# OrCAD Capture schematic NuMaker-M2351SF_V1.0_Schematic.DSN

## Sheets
1 Nu-Link2-Me: size A3; title: Nu-Link2-Me; rev: 1.0; company: CMHuang; note: Nu-Link2-Me
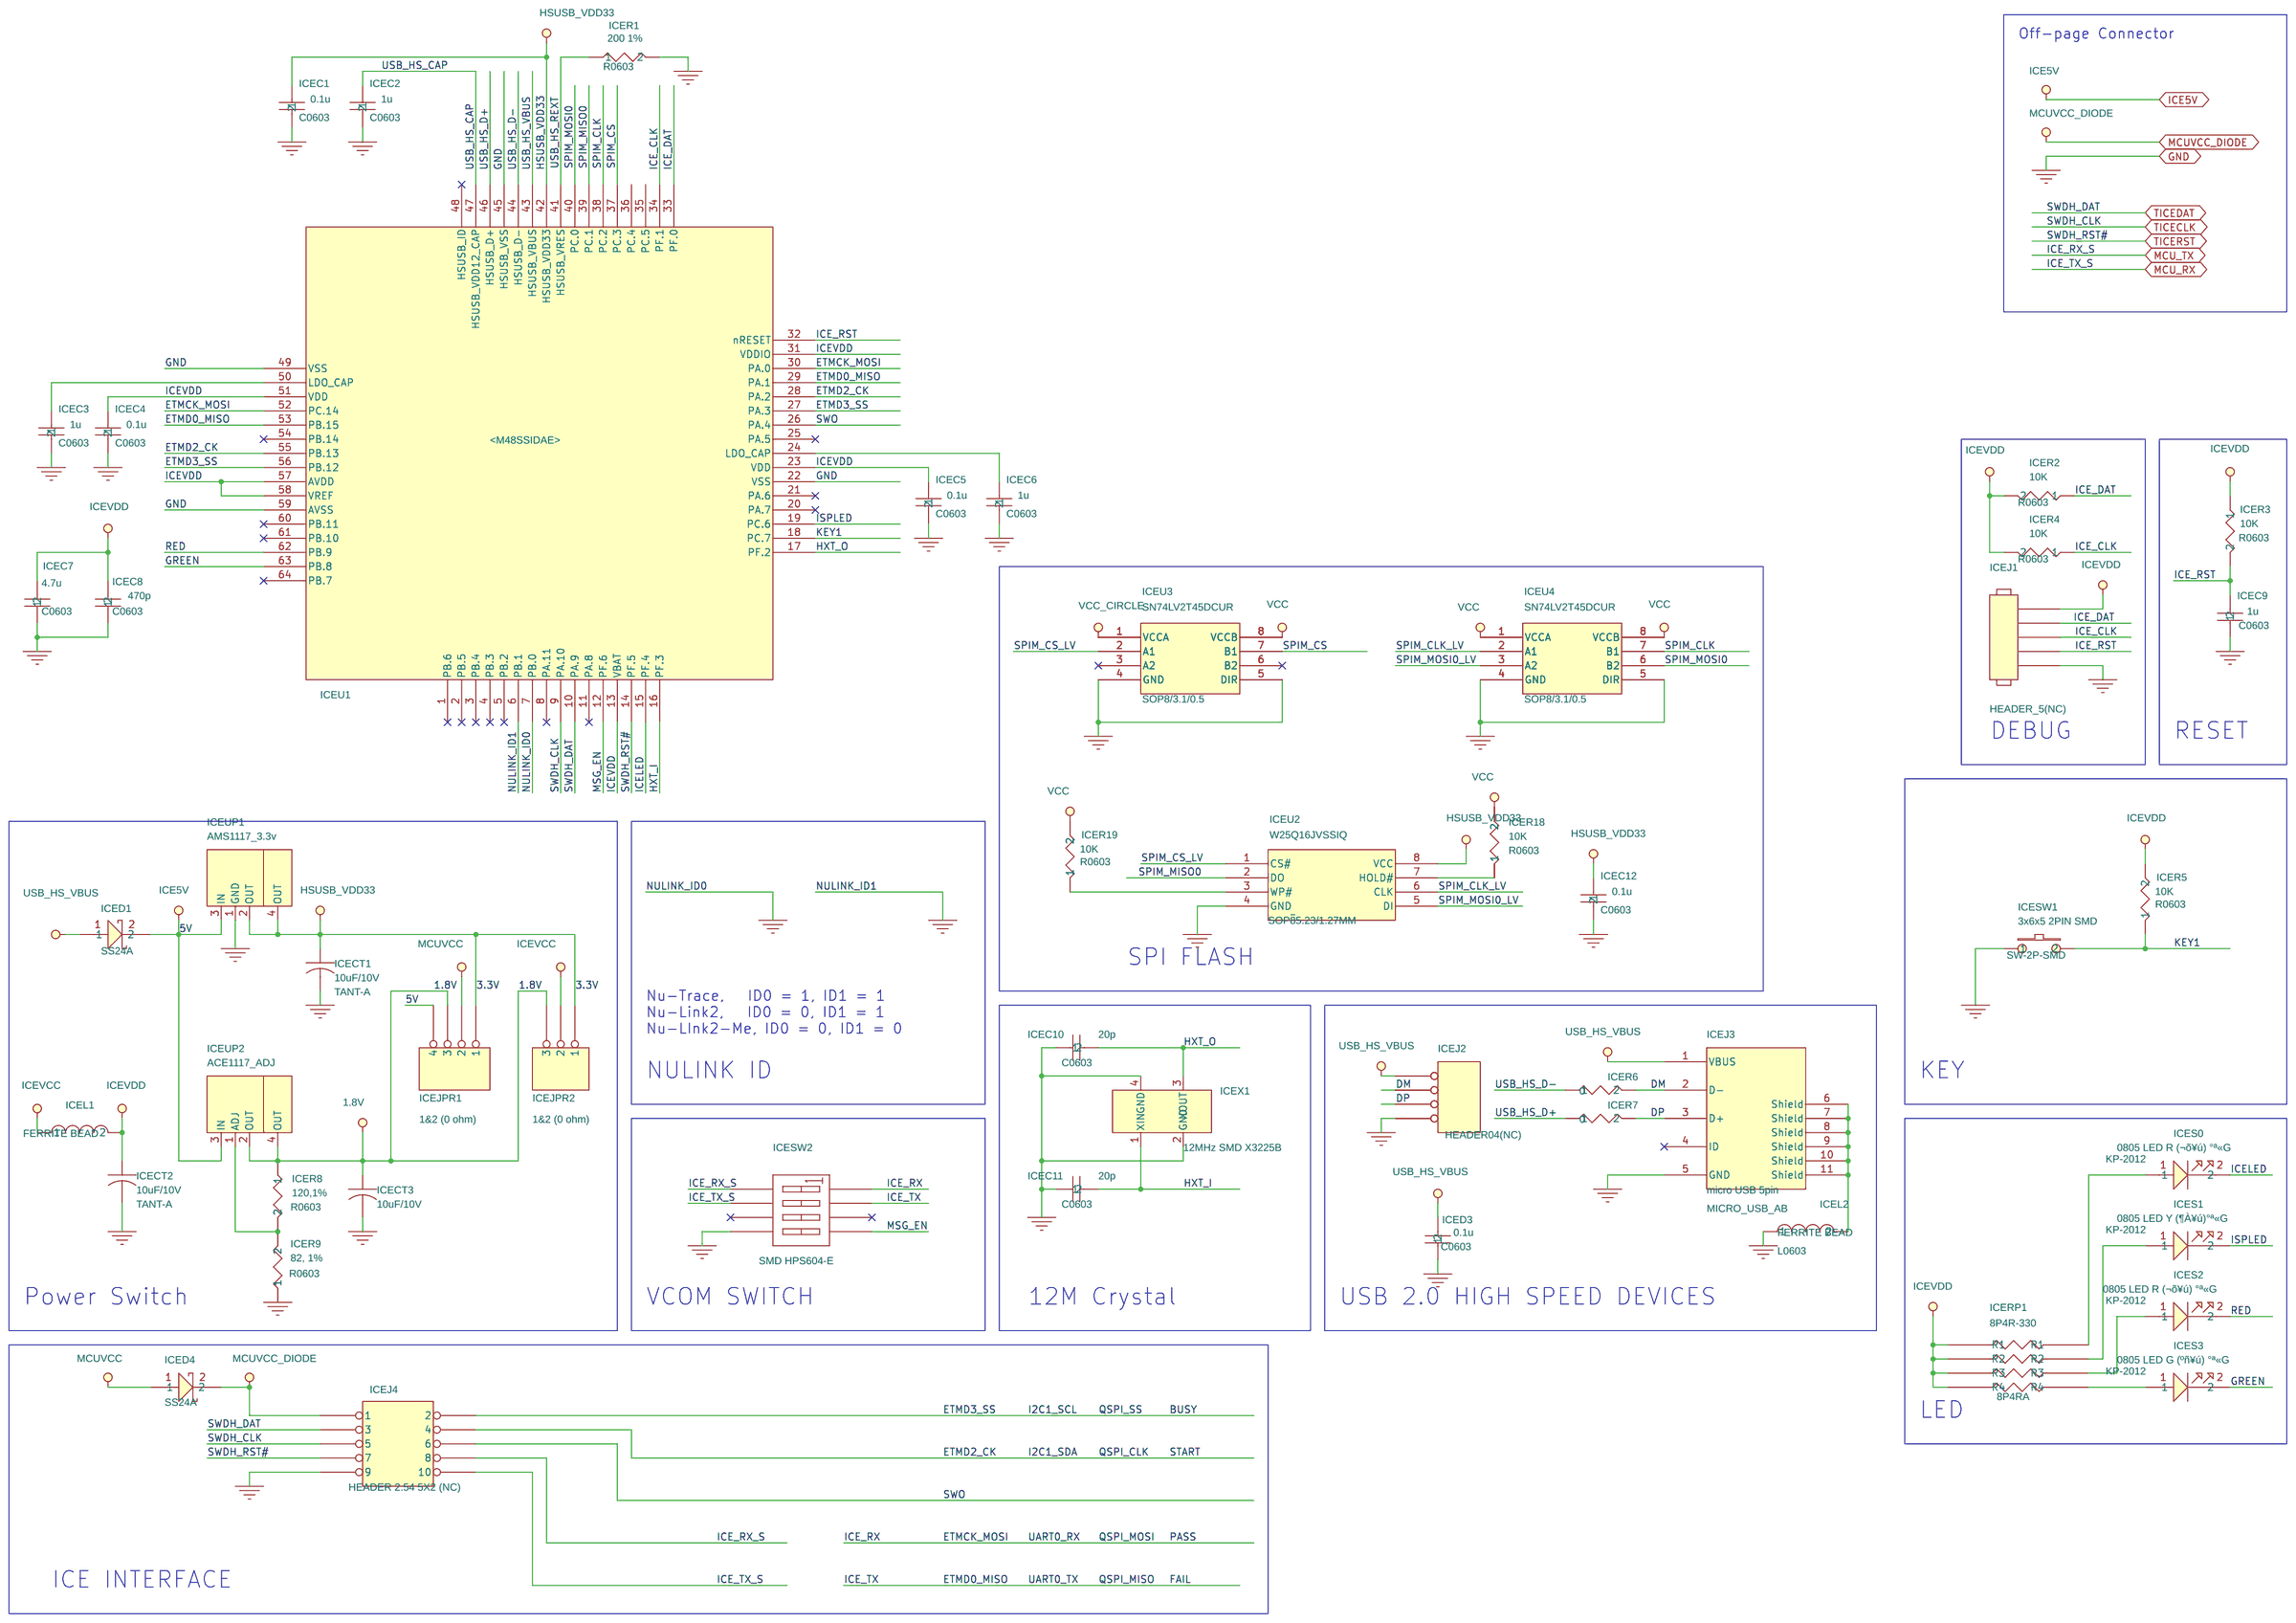
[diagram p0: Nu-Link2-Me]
2 M2351SFSIAAP: size Custom; title: M2351SFSIAAP; rev: v1.0; note: NuMaker-M2351SF
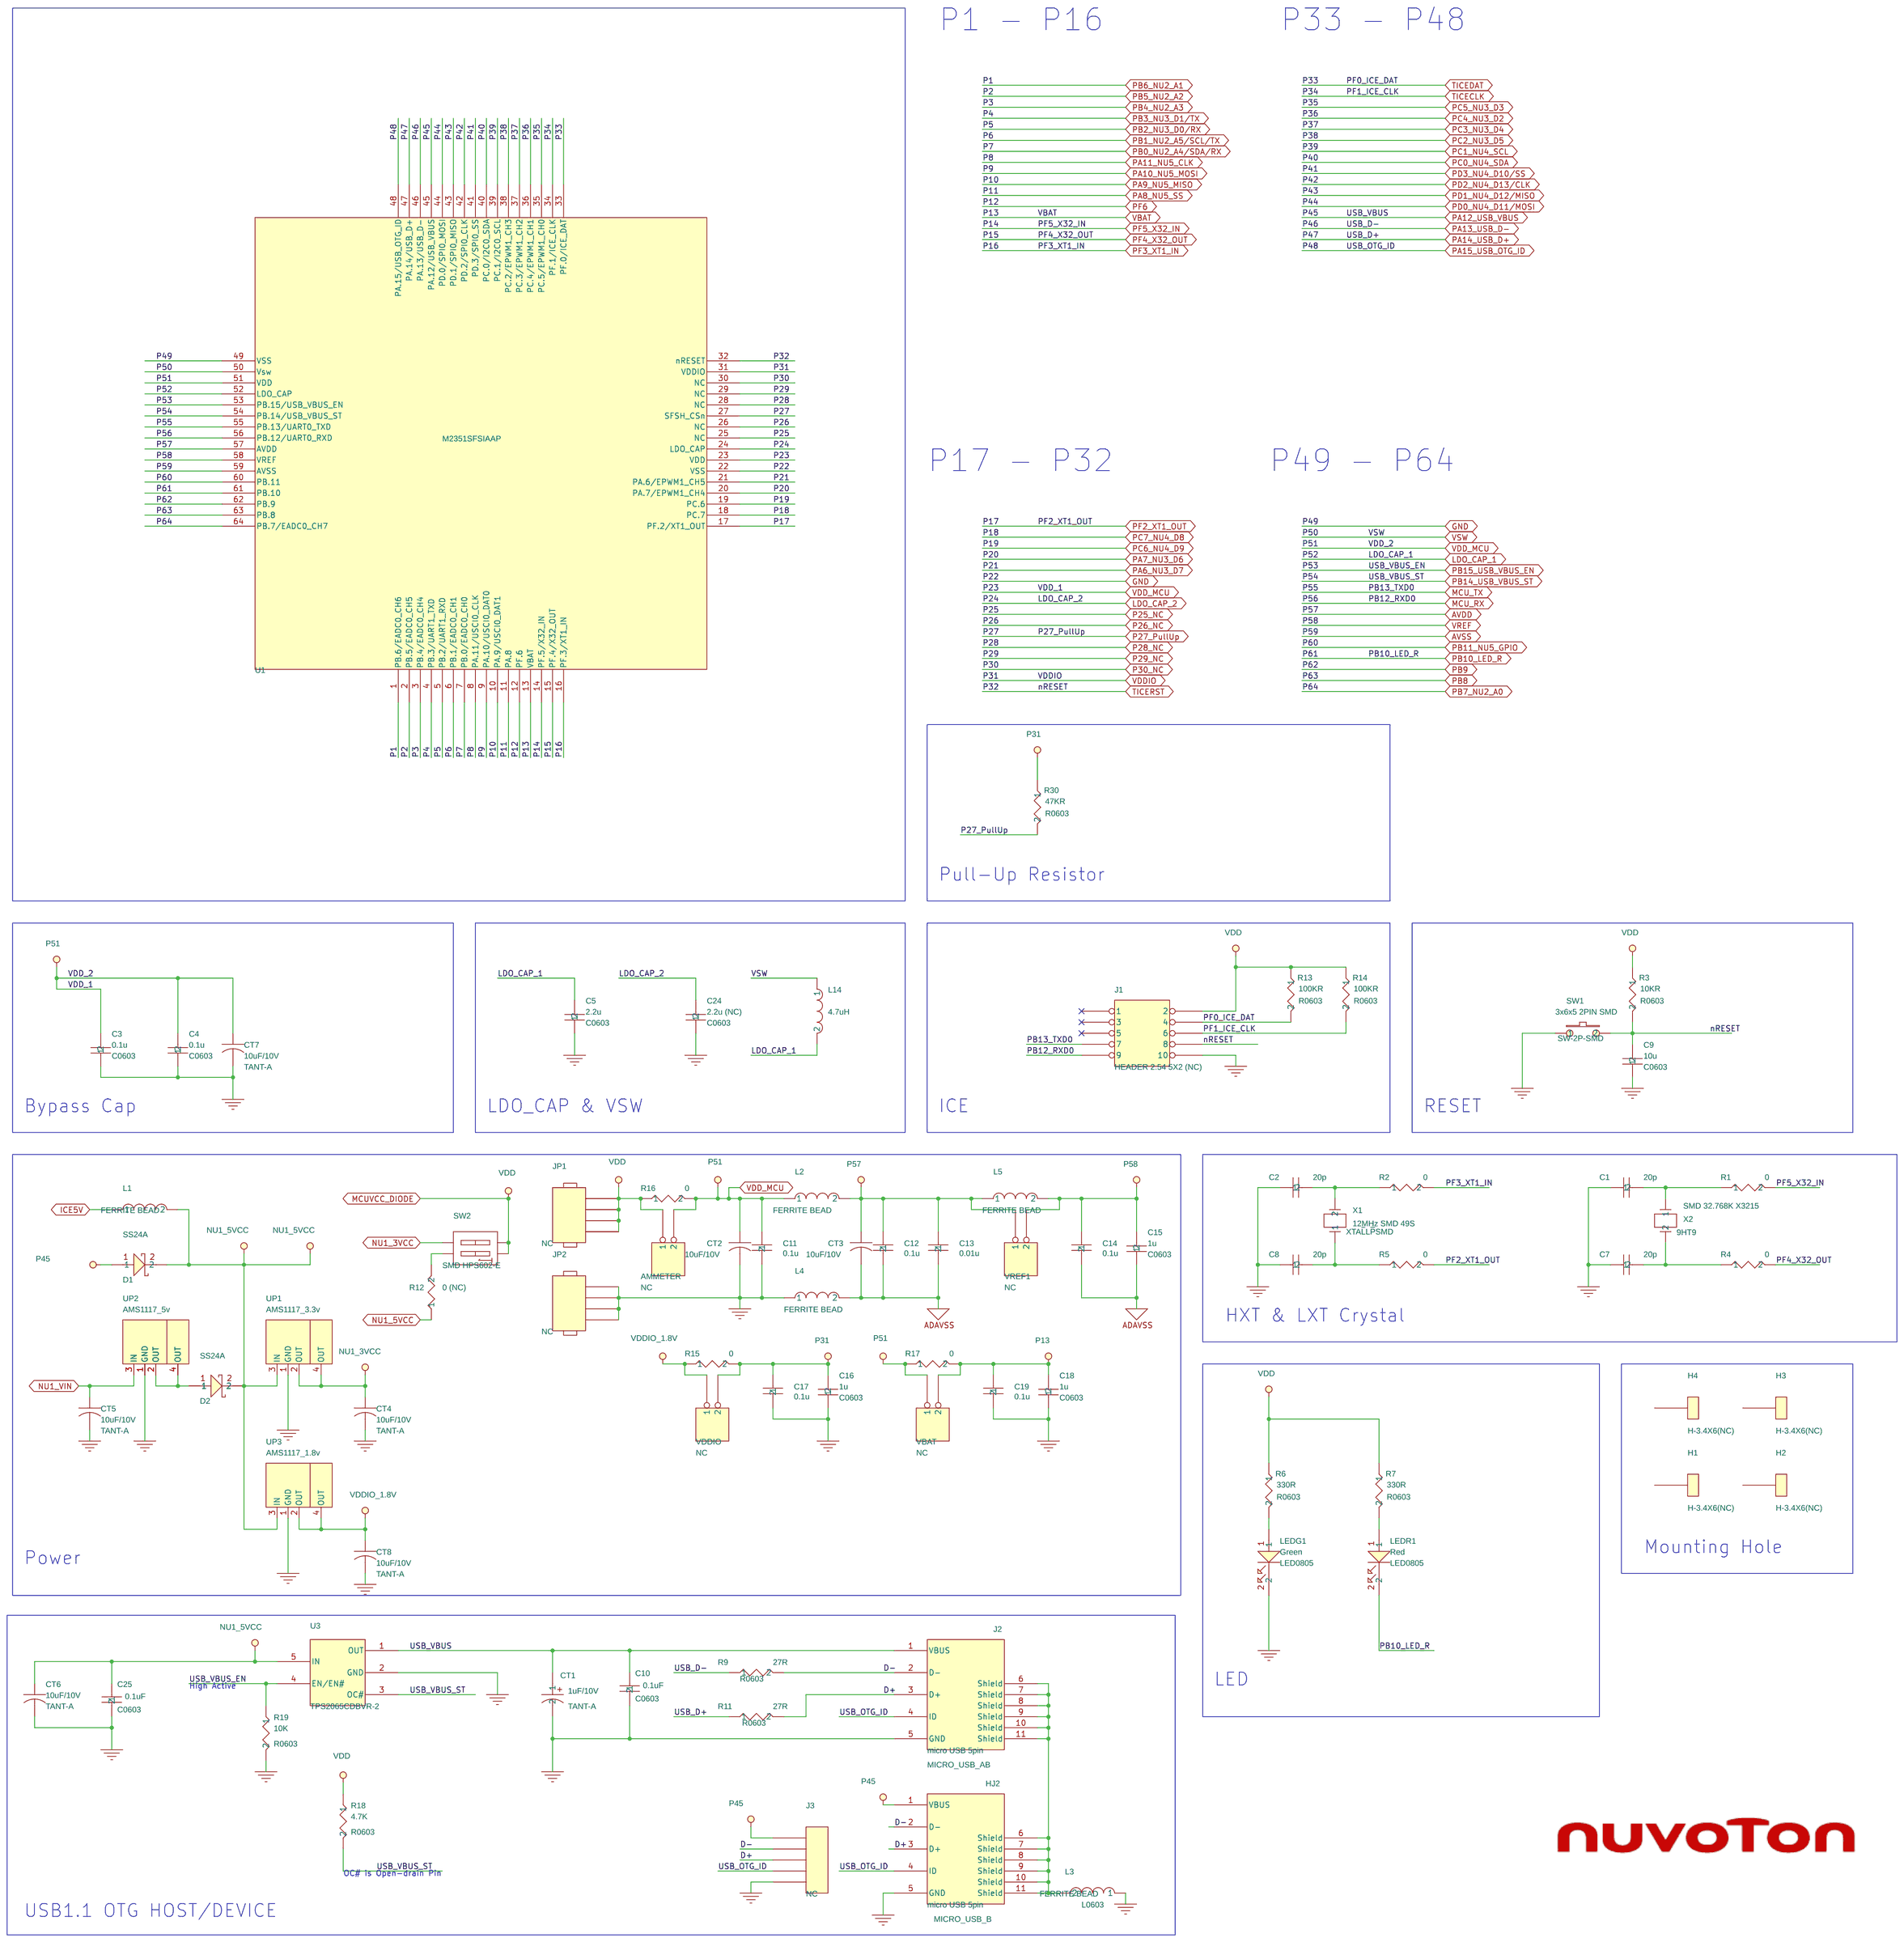
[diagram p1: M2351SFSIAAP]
3 Ext. Connector: size Custom; title: Ext. Connector; rev: v1.0; note: NuMaker-M2351SF
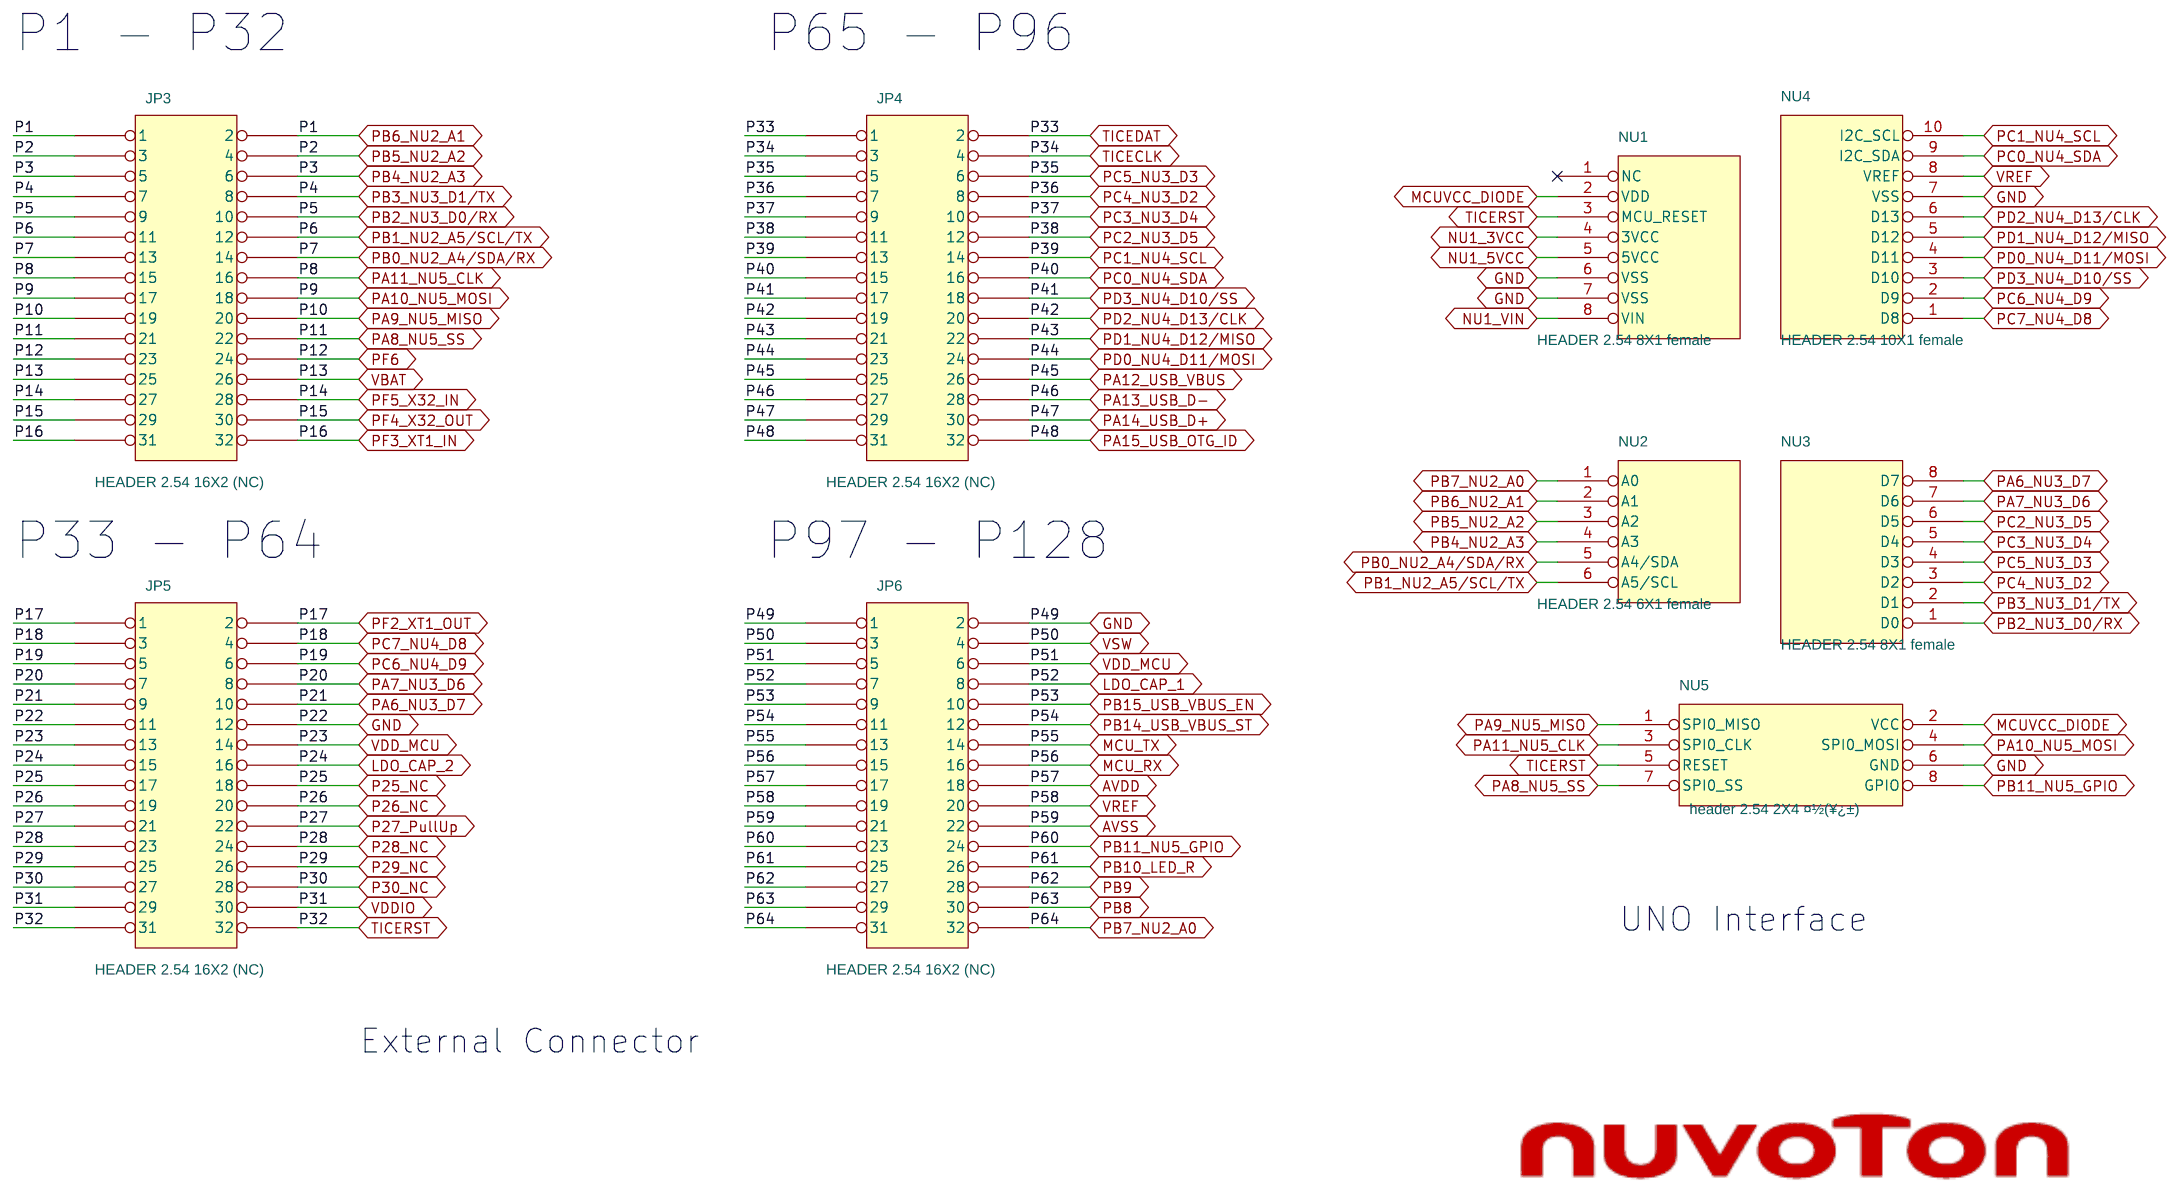
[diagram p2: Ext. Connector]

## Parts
sheet Ext. Connector
JP3  HEADER 2.54 16X2 (NC)  [HEADER16X2]
JP4  HEADER 2.54 16X2 (NC)  [HEADER16X2]
JP5  HEADER 2.54 16X2 (NC)  [HEADER16X2]
JP6  HEADER 2.54 16X2 (NC)  [HEADER16X2]
NU1  HEADER 2.54 8X1 female  [SIP-8P]
NU2  HEADER 2.54 6X1 female  [SIP-6P]
NU3  HEADER 2.54 8X1 female  [SIP-8P]
NU4  HEADER 2.54 10X1 female  [SIP-10P]
NU5  header 2.54 2X4 ¤½(¥¿­±)  [HEADER4X2]
sheet M2351SFSIAAP
AMMETER  NC  [HEADER2X1]
C1  20p  [C0603]
C2  20p  [C0603]
C3  0.1u  [C0603]
C4  0.1u  [C0603]
C5  2.2u  [C0603]
C7  20p  [C0603]
C8  20p  [C0603]
C9  10u  [C0603]
C10  0.1uF  [C0603]
C11  0.1u  [C0603]
C12  0.1u  [C0603]
C13  0.01u  [C0603]
C14  0.1u  [C0603]
C15  1u  [C0603]
C16  1u  [C0603]
C17  0.1u  [C0603]
C18  1u  [C0603]
C19  0.1u  [C0603]
C24  2.2u (NC)  [C0603]
C25  0.1uF  [C0603]
CT1  1uF/10V  [TANT-A]
CT2  10uF/10V  [TANT-A]
CT3  10uF/10V  [TANT-A]
CT4  10uF/10V  [TANT-A]
CT5  10uF/10V  [TANT-A]
CT6  10uF/10V  [TANT-A]
CT7  10uF/10V  [TANT-A]
CT8  10uF/10V  [TANT-A]
D1  SS24A  [RB060L]
D2  SS24A  [RB060L]
H1  H-3.4X6(NC)  [H-3.4X6]
H2  H-3.4X6(NC)  [H-3.4X6]
H3  H-3.4X6(NC)  [H-3.4X6]
H4  H-3.4X6(NC)  [H-3.4X6]
HJ2  micro USB 5pin  [MICRO_USB_B]
J1  HEADER 2.54 5X2 (NC)  [HEADER5X2]
J2  micro USB 5pin  [MICRO_USB_AB]
J3  NC  [HEADER5X1]
JP1  NC  [header1x4]
JP2  NC  [header1x4]
L1  FERRITE BEAD  [L0603]
L2  FERRITE BEAD  [L0603]
L3  FERRITE BEAD  [L0603]
L4  FERRITE BEAD  [L0603]
L5  FERRITE BEAD  [L0603]
L14  4.7uH  [L-VLF403215MT]
LEDG1  Green  [LED0805]
LEDR1  Red  [LED0805]
R1  0  [R0603]
R2  0  [R0603]
R3  10KR  [R0603]
R4  0  [R0603]
R5  0  [R0603]
R6  330R  [R0603]
R7  330R  [R0603]
R9  27R  [R0603]
R11  27R  [R0603]
R12  0 (NC)  [R0603]
R13  100KR  [R0603]
R14  100KR  [R0603]
R15  0  [R0603]
R16  0  [R0603]
R17  0  [R0603]
R18  4.7K  [R0603]
R19  10K  [R0603]
R30  47KR  [R0603]
SW1  3x6x5 2PIN SMD  [SW-2P-SMD]
SW2  SMD HPS602-E  [SW1X2]
U1  M2353SIAAE  [MCU_LQFP_64_7X7]
U3  TPS2065CDBVR-2  [SOT23-5]
UP1  AMS1117_3.3v  [SOT-223-1]
UP2  AMS1117_5v  [SOT-223-1]
UP3  AMS1117_1.8v  [SOT-223-1]
VBAT  NC  [HEADER2X1]
VDDIO  NC  [HEADER2X1]
VREF1  NC  [HEADER2X1]
X1  12MHz SMD 49S  [XTAL\LP\SMD]
X2  SMD 32.768K X3215  [9HT9]
sheet Nu-Link2-Me
ICEC1  0.1u  [C0603]
ICEC2  1u  [C0603]
ICEC3  1u  [C0603]
ICEC4  0.1u  [C0603]
ICEC5  0.1u  [C0603]
ICEC6  1u  [C0603]
ICEC7  4.7u  [C0603]
ICEC8  470p  [C0603]
ICEC9  1u  [C0603]
ICEC10  20p  [C0603]
ICEC11  20p  [C0603]
ICEC12  0.1u  [C0603]
ICECT1  10uF/10V  [TANT-A]
ICECT2  10uF/10V  [TANT-A]
ICECT3  10uF/10V  [TANT-A]
ICED1  SS24A  [RB060L]
ICED3  0.1u  [C0603]
ICED4  SS24A  [RB060L]
ICEJ1  HEADER_5(NC)  [HEADER5X1]
ICEJ2  HEADER04(NC)  [HEADER04]
ICEJ3  micro USB 5pin  [MICRO_USB_AB]
ICEJ4  HEADER 2.54 5X2 (NC)  [HEADER5X2]
ICEJPR1  1&2 (0 ohm)  [R0603X3]
ICEJPR2  1&2 (0 ohm)  [R0603X2]
ICEL1  FERRITE BEAD  [L0603]
ICEL2  FERRITE BEAD  [L0603]
ICER1  200 1%  [R0603]
ICER2  10K  [R0603]
ICER3  10K  [R0603]
ICER4  10K  [R0603]
ICER5  10K  [R0603]
ICER6  0  [R0603]
ICER7  0  [R0603]
ICER8  120,1%  [R0603]
ICER9  82, 1%  [R0603]
ICER18  10K  [R0603]
ICER19  10K  [R0603]
ICERP1  8P4R-330  [8P4RA]
ICES0  0805 LED R (¬õ¥ú) °ª«G  [KP-2012]
ICES1  0805 LED Y (¶À¥ú)°ª«G  [KP-2012]
ICES2  0805 LED R (¬õ¥ú) °ª«G  [KP-2012]
ICES3  0805 LED G (ºñ¥ú) °ª«G  [KP-2012]
ICESW1  3x6x5 2PIN SMD  [SW-2P-SMD]
ICESW2  SMD HPS604-E  [SW1X4]
ICEU1  M48SSIDAE  [LQFP64_7x7_M48SSIDAE]
ICEU2  W25Q16JVSSIQ  [SOP8\5.23/1.27MM]
ICEU3  SN74LV2T45DCUR  [SOP8/3.1/0.5]
ICEU4  SN74LV2T45DCUR  [SOP8/3.1/0.5]
ICEUP1  AMS1117_3.3v  [SOT-223-1]
ICEUP2  ACE1117_ADJ  [SOT-223-1]
ICEX1  12MHz SMD X3225B  [CRYSTAL_SMD]

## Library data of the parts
JP3 = HEADER_16X2_2
JP4 = HEADER_16X2_3
JP5 = HEADER_16X2_1
JP6 = HEADER_16X2
NU1 = POWER_CONNECT_0
NU2 = ADC_CONNECT_0
NU3 = PWM0_CONNECT_0
NU4 = PWM1_CONNECT_1
NU5 = NuEdu_NU7
AMMETER = HEADER_2_2
C1 = C_20p_3
C2 = C_20p
C3 = CAP-C: Package: 0603; element_no: C0004
C4 = CAP-C_1: Package: 0603; element_no: C0004
C5 = CAP-C_3: Package: 0603; element_no: C0006
C7 = C_20p_1
C8 = C_20p_2
C9 = CAP-C_6: Package: 0603; element_no: C0006
C10 = CAP-B_1: Package: 0603
C11 = C_0.1u_1: element_no: C0004
C12 = C_0.1u_3: element_no: C0004
C13 = C_0.1u_5: element_no: C0003
C14 = C_0.1u_2: element_no: C0004
C15 = CAP-C_4: Package: 0603; element_no: C0006
C16 = CAP-C_7: Package: 0603; element_no: C0006
C17 = C_0.1u_4: element_no: C0004
C18 ICEC6 = CAP-C_2: Package: 0603; element_no: C0006
C19 = C_0.1u: element_no: C0004
C24 = CAP-C_5: Package: 0603; element_no: C0006
C25 = CAP-B: Package: 0603
CT1 = CAP-T: Package: TANT-R
CT2-CT8 ICECT1-ICECT3 = C_10uF_10V
D1 ICED4 = D_SS24A
D2 ICED1 = D_SS24A_1
H1-H4 = TEST_POINT
HJ2 ICEJ3 J2 = micro_USB_5pin_0
ICEJ4 J1 = HEADER_5X2
J3 = CON5
JP1 JP2 = HEADER_4_v2
L1 = FERRITE_BEAD_4
L2 = FERRITE_BEAD_3
L3 = FERRITE_BEAD_2
ICEL2 L4 = FERRITE_BEAD_1
ICEL1 L5 = FERRITE_BEAD
L14 = INDUCTOR
LEDG1 = LED_0_1: Package: KP-2012; Vendor: Kingbright
LEDR1 = LED_0: Package: KP-2012; Vendor: Kingbright
R1 = R_0_1
R2 = R_0_5
ICER1 R3 = R_0_6: Package: 0603
R4 = R_0_16
R5 = R_0_4
R6 = R_0_12: Package: 0603
ICER2 R7 = R_0: Package: 0603
ICER8 R9 = R_0_8: Package: 0603
R11 = R_0_15: Package: 0603
R12 = R_0_11
R13 = R_0_10: Package: 0603
R14 = R_0_13: Package: 0603
R15 = R_0_9
R16 = R_0_2
R17 = R_0_17
ICER9 R18 = R_0_7: Package: 0603
ICER18 R19 = R_0_3: Package: 0603
R30 = R_0_14: Package: 0603
ICESW1 SW1 = SW_PUSHBUTTON_0
SW2 = SW_DIP-4_2
U1 = M2353SIAAE_2: M2351SIAAE: M2351SFSIAAP
U3 = NCT3520U
ICEUP1 UP1-UP3 = TO-247_Regulator_10
VBAT = HEADER_2_1
VDDIO = HEADER_2_3
VREF1 = HEADER_2
X1 = Xtal_12MHz
X2 = Xtal_32.768K
ICEC1 = CAP-C_8: Package: 0603; element_no: C0004
ICEC2 = CAP-C_11: Package: 0603; element_no: C0006
ICEC3 = CAP-C_10: Package: 0603; element_no: C0006
ICEC4 = CAP-C_12: Package: 0603; element_no: C0004
ICEC5 = CAP-C_5: Package: 0603; element_no: C0004
ICEC7 = CAP-C_3: Package: 0603
ICEC8 = CAP-C_6: Package: 0603
ICEC9 = CAP-C_9: Package: 0603; element_no: C0006
ICEC10 = CAP-C_1: Package: 0603
ICEC11 = CAP-C: Package: 0603
ICEC12 = CAP-C_4: Package: 0603; element_no: C0004
ICED3 = CAP-C_7: Package: 0603; element_no: C0004
ICEJ1 = HEADER_5
ICEJ2 = HEADER_4
ICEJPR1 = HEADER_3_0
ICEJPR2 = HEADER_3
ICER3 = R_0_4: Package: 0603
ICER4 = R_0_1: Package: 0603
ICER5 = R_0_5: Package: 0603
ICER6 = R_33_1
ICER7 = R_33
ICER19 = R_0_2: Package: 0603
ICERP1 = R-PACK8_0
ICES0 = LED_0_1: Vendor: Kingbright
ICES1 = LED_0_3: Vendor: Kingbright
ICES2 = LED_0_2: Vendor: Kingbright
ICES3 = LED_0: Vendor: Kingbright
ICESW2 = SW_DIP-4_SM
ICEU1 = M487SIDAE_0: M487SIDAE: <M48SSIDAE>
ICEU2 = W25P10_20_40_SOIC_0: Package: SOP8; Vendor: WINBOND
ICEU3 ICEU4 = SN74LV2T45
ICEUP2 = TO-247_Regulator_0
ICEX1 = Crystal_SMD_1

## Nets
1.8V: ICECT3.1 ICEJPR1.3 ICEJPR2.3 ICER8.1 ICEUP2.2(OUT) ICEUP2.4(OUT)
3.3V: ICEC1.1 ICEC12.1 ICECT1.1 ICEJPR1.1 ICEJPR2.1 ICER18.2 ICER19.2 ICEU1.42(HSUSB_VDD33) ICEU2.8(VCC) ICEU3.1(VCCA) ICEU4.1(VCCA) ICEUP1.2(OUT) ICEUP1.4(OUT)
AVDD: C12.1 C13.1 CT3.1 JP6.17 JP6.18 L2.2 L5.1 U1.57(AVDD) VREF1.1
AVSS: C12.2 C13.2 C14.2 C15.1 CT3.2 JP6.21 JP6.22 L4.2 U1.59(AVSS)
GND: C1.1 C2.1 C3.1 C4.1 C5.1 C7.1 C8.1 C9.1 C10.2 C11.2 C16.1 C17.2 C18.1 C19.2 C24.1 C25.2 CT1.2 CT2.2 CT4.2 CT5.2 CT6.2 CT7.2 CT8.2 HJ2.5(GND) ICEC1.2 ICEC2.2 ICEC3.2 ICEC4.2 ICEC5.2 ICEC6.2 ICEC7.1 ICEC8.1 ICEC9.1 ICEC10.1 ICEC11.1 ICEC12.2 ICECT1.2 ICECT2.2 ICECT3.2 ICED3.1 ICEJ1.5 ICEJ2.4 ICEJ3.5(GND) ICEJ4.9 ICEL2.1 ICER1.2 ICER9.1 ICESW1.1 ICESW2.4(A4) ICEU1.6(PB.1) ICEU1.7(PB.0) ICEU1.22(VSS) ICEU1.45(HSUSB_VSS) ICEU1.49(VSS) ICEU1.59(AVSS) ICEU2.4(GND) ICEU3.4(GND) ICEU3.5(DIR) ICEU4.4(GND) ICEU4.5(DIR) ICEUP1.1(GND) ICEX1.2(GND) ICEX1.4(GND) J1.10 J2.5(GND) J3.5 JP2.1 JP2.2 JP2.3 JP2.4 JP5.11 JP5.12 JP6.1 JP6.2 L3.1 L4.1 LEDG1.2 NU1.6(VSS) NU1.7(VSS) NU4.7(VSS) NU5.6(GND) R19.2 SW1.1 U1.22(VSS) U1.49(VSS) U3.2(GND) UP1.1(GND) UP2.1(GND) UP3.1(GND)
VBAT: C18.2 C19.1 JP3.25 JP3.26 R17.2 U1.13(VBAT) VBAT.2
VDD: AMMETER.1 ICED4.2 ICEJ4.1 J1.2 JP1.1 JP1.2 JP1.3 JP1.4 NU1.2(VDD) NU5.2(VCC) R3.1 R6.1 R7.1 R13.1 R14.1 R16.1 R18.1 SW2.3(B1) SW2.4(B2)
VDD_MCU: AMMETER.2 C3.2 C4.2 C11.1 CT2.1 CT7.1 JP5.13 JP5.14 JP6.5 JP6.6 L2.1 R16.2 R17.1 U1.23(VDD) U1.51(VDD) VBAT.1
VDDIO: C16.2 C17.1 JP5.29 JP5.30 R15.2 R30.1 U1.31(VDDIO) VDDIO.2
VDDIO_1.8V: CT8.1 R15.1 UP3.2(OUT) UP3.4(OUT) VDDIO.1
BUSY: ICEJ4.2 ICEU1.27(PA.3) ICEU1.56(PB.12)
D+: HJ2.3(D+) J2.3(D+) J3.3 R11.2
D-: HJ2.2(D-) J2.2(D-) J3.2 R9.2
DM: ICEJ2.2 ICEJ3.2(D-) ICER6.2
DP: ICEJ2.3 ICEJ3.3(D+) ICER7.2
ETMD2_CK: ICEJ4.4 ICEU1.28(PA.2) ICEU1.55(PB.13)
GREEN: ICES3.2 ICEU1.63(PB.8)
HXT_I: ICEC11.2 ICEU1.16(PF.3) ICEX1.1(XIN)
HXT_O: ICEC10.2 ICEU1.17(PF.2) ICEX1.3(XOUT)
ICE5V: ICED1.2 ICEJPR1.4 ICEUP1.3(IN) ICEUP2.3(IN) L1.1
ICE_CLK: ICEJ1.3 ICER4.1 ICEU1.34(PF.1)
ICE_DAT: ICEJ1.2 ICER2.1 ICEU1.33(PF.0)
ICE_RST: ICEC9.2 ICEJ1.4 ICER3.2 ICEU1.32(nRESET)
ICE_RX: ICESW2.8(B1) ICEU1.30(PA.0) ICEU1.52(PC.14)
ICE_TX: ICESW2.7(B2) ICEU1.29(PA.1) ICEU1.53(PB.15)
ICELED: ICES0.2 ICEU1.15(PF.4)
ICEVCC: ICEJPR2.2 ICEL1.1
ICEVDD: ICEC4.1 ICEC5.1 ICEC7.2 ICEC8.2 ICECT2.1 ICEJ1.1 ICEL1.2 ICER2.2 ICER3.1 ICER4.2 ICER5.2 ICERP1.1(R1) ICERP1.3(R2) ICERP1.5(R3) ICERP1.7(R4) ICEU1.13(VBAT) ICEU1.23(VDD) ICEU1.31(VDDIO) ICEU1.51(VDD) ICEU1.57(AVDD) ICEU1.58(VREF) ICEU3.8(VCCB) ICEU4.8(VCCB)
ISPLED: ICES1.2 ICEU1.19(PC.6)
KEY1: ICER5.1 ICESW1.2 ICEU1.18(PC.7)
LDO_CAP_1: C5.2 JP6.7 JP6.8 L14.2 U1.52(LDO_CAP)
LDO_CAP_2: C24.2 JP5.15 JP5.16 U1.24(LDO_CAP)
MCU_RX: ICEJ4.10 ICESW2.2(A2) J1.9 JP6.15 JP6.16 U1.56(PB.12/UART0_RXD)
MCU_TX: ICEJ4.8 ICESW2.1(A1) J1.7 JP6.13 JP6.14 U1.55(PB.13/UART0_TXD)
MCUVCC: ICED4.1 ICEJPR1.2
MSG_EN: ICESW2.5(B4) ICEU1.12(PF.6)
NU1_3VCC: CT4.1 NU1.4(3VCC) SW2.2(A2) UP1.2(OUT) UP1.4(OUT)
NU1_5VCC: C25.1 CT6.1 D1.2 D2.2 L1.2 NU1.5(5VCC) R12.1 U3.5(IN) UP1.3(IN) UP3.3(IN)
NU1_VIN: CT5.1 NU1.8(VIN) UP2.3(IN)
P25_NC: JP5.17 JP5.18 U1.25(NC)
P26_NC: JP5.19 JP5.20 U1.26(NC)
P27_PullUp: JP5.21 JP5.22 R30.2 U1.27(SFSH_CSn)
P28_NC: JP5.23 JP5.24 U1.28(NC)
P29_NC: JP5.25 JP5.26 U1.29(NC)
P30_NC: JP5.27 JP5.28 U1.30(NC)
PA6_NU3_D7: JP5.9 JP5.10 NU3.8(D7) U1.21(PA.6/EPWM1_CH5)
PA7_NU3_D6: JP5.7 JP5.8 NU3.7(D6) U1.20(PA.7/EPWM1_CH4)
PA8_NU5_SS: JP3.21 JP3.22 NU5.7(SPI0_SS) U1.11(PA.8)
PA9_NU5_MISO: JP3.19 JP3.20 NU5.1(SPI0_MISO) U1.10(PA.9/USCI0_DAT1)
PA10_NU5_MOSI: JP3.17 JP3.18 NU5.4(SPI0_MOSI) U1.9(PA.10/USCI0_DAT0)
PA11_NU5_CLK: JP3.15 JP3.16 NU5.3(SPI0_CLK) U1.8(PA.11/USCI0_CLK)
PA12_USB_VBUS: C10.1 CT1.1 D1.1 HJ2.1(VBUS) J2.1(VBUS) J3.1 JP4.25 JP4.26 U1.45(PA.12/USB_VBUS) U3.1(OUT)
PA13_USB_D-: JP4.27 JP4.28 R9.1 U1.46(PA.13/USB_D-)
PA14_USB_D+: JP4.29 JP4.30 R11.1 U1.47(PA.14/USB_D+)
PA15_USB_OTG_ID: HJ2.4(ID) J2.4(ID) J3.4 JP4.31 JP4.32 U1.48(PA.15/USB_OTG_ID)
PB0_NU2_A4/SDA/RX: JP3.13 JP3.14 NU2.5(A4/SDA) U1.7(PB.0/EADC0_CH0)
PB1_NU2_A5/SCL/TX: JP3.11 JP3.12 NU2.6(A5/SCL) U1.6(PB.1/EADC0_CH1)
PB2_NU3_D0/RX: JP3.9 JP3.10 NU3.1(D0) U1.5(PB.2/UART1_RXD)
PB3_NU3_D1/TX: JP3.7 JP3.8 NU3.2(D1) U1.4(PB.3/UART1_TXD)
PB4_NU2_A3: JP3.5 JP3.6 NU2.4(A3) U1.3(PB.4/EADC0_CH4)
PB5_NU2_A2: JP3.3 JP3.4 NU2.3(A2) U1.2(PB.5/EADC0_CH5)
PB6_NU2_A1: JP3.1 JP3.2 NU2.2(A1) U1.1(PB.6/EADC0_CH6)
PB7_NU2_A0: JP6.31 JP6.32 NU2.1(A0) U1.64(PB.7/EADC0_CH7)
PB8: JP6.29 JP6.30 U1.63(PB.8)
PB9: JP6.27 JP6.28 U1.62(PB.9)
PB10_LED_R: JP6.25 JP6.26 LEDR1.2 U1.61(PB.10)
PB11_NU5_GPIO: JP6.23 JP6.24 NU5.8(GPIO) U1.60(PB.11)
PB14_USB_VBUS_ST: JP6.11 JP6.12 R18.2 U1.54(PB.14/USB_VBUS_ST) U3.3(OC#)
PB15_USB_VBUS_EN: JP6.9 JP6.10 R19.1 U1.53(PB.15/USB_VBUS_EN) U3.4(EN/EN#)
PC0_NU4_SDA: JP4.15 JP4.16 NU4.9(I2C_SDA) U1.40(PC.0/I2C0_SDA)
PC1_NU4_SCL: JP4.13 JP4.14 NU4.10(I2C_SCL) U1.39(PC.1/I2C0_SCL)
PC2_NU3_D5: JP4.11 JP4.12 NU3.6(D5) U1.38(PC.2/EPWM1_CH3)
PC3_NU3_D4: JP4.9 JP4.10 NU3.5(D4) U1.37(PC.3/EPWM1_CH2)
PC4_NU3_D2: JP4.7 JP4.8 NU3.3(D2) U1.36(PC.4/EPWM1_CH1)
PC5_NU3_D3: JP4.5 JP4.6 NU3.4(D3) U1.35(PC.5/EPWM1_CH0)
PC6_NU4_D9: JP5.5 JP5.6 NU4.2(D9) U1.19(PC.6)
PC7_NU4_D8: JP5.3 JP5.4 NU4.1(D8) U1.18(PC.7)
PD0_NU4_D11/MOSI: JP4.23 JP4.24 NU4.4(D11) U1.44(PD.0/SPI0_MOSI)
PD1_NU4_D12/MISO: JP4.21 JP4.22 NU4.5(D12) U1.43(PD.1/SPI0_MISO)
PD2_NU4_D13/CLK: JP4.19 JP4.20 NU4.6(D13) U1.42(PD.2/SPI0_CLK)
PD3_NU4_D10/SS: JP4.17 JP4.18 NU4.3(D10) U1.41(PD.3/SPI0_SS)
PF2_XT1_OUT: JP5.1 JP5.2 R5.2 U1.17(PF.2/XT1_OUT)
PF3_XT1_IN: JP3.31 JP3.32 R2.2 U1.16(PF.3/XT1_IN)
PF4_X32_OUT: JP3.29 JP3.30 R4.2 U1.15(PF.4/X32_OUT)
PF5_X32_IN: JP3.27 JP3.28 R1.2 U1.14(PF.5/X32_IN)
PF6: JP3.23 JP3.24 U1.12(PF.6)
RED: ICES2.2 ICEU1.62(PB.9)
SPIM_CLK: ICEU1.38(PC.2) ICEU4.7(B1)
SPIM_CLK_LV: ICEU2.6(CLK) ICEU4.2(A1)
SPIM_CS: ICEU1.37(PC.3) ICEU3.7(B1)
SPIM_CS_LV: ICEU2.1(CS#) ICEU3.2(A1)
SPIM_MISO0: ICEU1.39(PC.1) ICEU2.2(DO)
SPIM_MOSI0: ICEU1.40(PC.0) ICEU4.6(B2)
SPIM_MOSI0_LV: ICEU2.5(DI) ICEU4.3(A2)
SWO: ICEJ4.6 ICEU1.26(PA.4)
TICECLK: ICEJ4.5 ICEU1.9(PA.10) J1.6 JP4.3 JP4.4 R14.2 U1.34(PF.1/ICE_CLK)
TICEDAT: ICEJ4.3 ICEU1.10(PA.9) J1.4 JP4.1 JP4.2 R13.2 U1.33(PF.0/ICE_DAT)
TICERST: C9.2 ICEJ4.7 ICEU1.14(PF.5) J1.8 JP5.31 JP5.32 NU1.3(MCU_RESET) NU5.5(RESET) R3.2 SW1.2 U1.32(nRESET)
USB_HS_CAP: ICEC2.1 ICEU1.47(HSUSB_VDD12_CAP)
USB_HS_D+: ICER7.1 ICEU1.46(HSUSB_D+)
USB_HS_D-: ICER6.1 ICEU1.44(HSUSB_D-)
USB_HS_REXT: ICER1.1 ICEU1.41(HSUSB_VRES)
USB_HS_VBUS: ICED1.1 ICED3.2 ICEJ2.1 ICEJ3.1(VBUS) ICEU1.43(HSUSB_VBUS)
VREF: C14.1 C15.2 JP6.19 JP6.20 L5.2 NU4.8(VREF) U1.58(VREF) VREF1.2
VSW: JP6.3 JP6.4 L14.1 U1.50(Vsw)
N16825237: LEDG1.1 R6.2
N16825240: LEDR1.1 R7.2
N16840819: ICEC6.1 ICEU1.24(LDO_CAP)
N16840960: ICEC3.1 ICEU1.50(LDO_CAP)
N17019924: ICER8.2 ICER9.2 ICEUP2.1(ADJ)
N17029977: ICERP1.8(R4) ICES3.1
N17029979: ICERP1.6(R3) ICES2.1
N17030004: ICERP1.4(R2) ICES1.1
N17030010: ICERP1.2(R1) ICES0.1
N17042369: ICEJ3.6(Shield) ICEJ3.7(Shield) ICEJ3.8(Shield) ICEJ3.9(Shield) ICEJ3.10(Shield) ICEJ3.11(Shield) ICEL2.2
N17125028: R12.2 SW2.1(A1)
N17155328: ICER18.1 ICEU2.7(HOLD#)
N17155343: ICER19.1 ICEU2.3(WP#)
N17159369: C8.2 R5.1 X1.1
N17159371: C2.2 R2.1 X1.2
N17159463: C1.2 R1.1 X2.1
N17159465: C7.2 R4.1 X2.2
N17167442: D2.1 UP2.2(OUT) UP2.4(OUT)
N17319437: HJ2.6(Shield) HJ2.7(Shield) HJ2.8(Shield) HJ2.9(Shield) HJ2.10(Shield) HJ2.11(Shield) J2.6(Shield) J2.7(Shield) J2.8(Shield) J2.9(Shield) J2.10(Shield) J2.11(Shield) L3.2

Not connected (* = marked no-connect by the designer): H1 1; H2 1; H3 1; H4 1; ICEJ3 4(ID)*; ICESW2 3(A3)* 6(B3)*; ICEU1 1(PB.6)* 2(PB.5)* 3(PB.4)* 4(PB.3)* 5(PB.2)* 8(PA.11)* 11(PA.8)* 20(PA.7)* 21(PA.6)* 25(PA.5)* 35(PC.5) 36(PC.4) 48(HSUSB_ID)* 54(PB.14)* 60(PB.11)* 61(PB.10)* 64(PB.7)*; ICEU3 3(A2)* 6(B2)*; J1 1* 3* 5*; NU1 1(NC)*

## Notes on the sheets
sheet 1
- Off-page Connector
- DEBUG
- RESET
- SPI FLASH
- Nu-Trace,   ID0 = 1, ID1 = 1
  Nu-Link2,   ID0 = 0, ID1 = 1
  Nu-LInk2-Me, ID0 = 0, ID1 = 0
- NULINK ID
- KEY
- Power Switch
- VCOM SWITCH
- 12M Crystal
- USB 2.0 HIGH SPEED DEVICES
- LED
- ICE INTERFACE
sheet 2
- P1 - P16
- P33 - P48
- P17 - P32
- P49 - P64
- Pull-Up Resistor
- Bypass Cap
- LDO_CAP & VSW
- ICE
- RESET
- HXT & LXT Crystal
- Mounting Hole
- Power
- LED
- High Active
- OC# is Open-drain Pin
- USB1.1 OTG HOST/DEVICE
sheet 3
- P1 - P32
- P65 - P96
- P33 - P64
- P97 - P128
- UNO Interface
- External Connector
